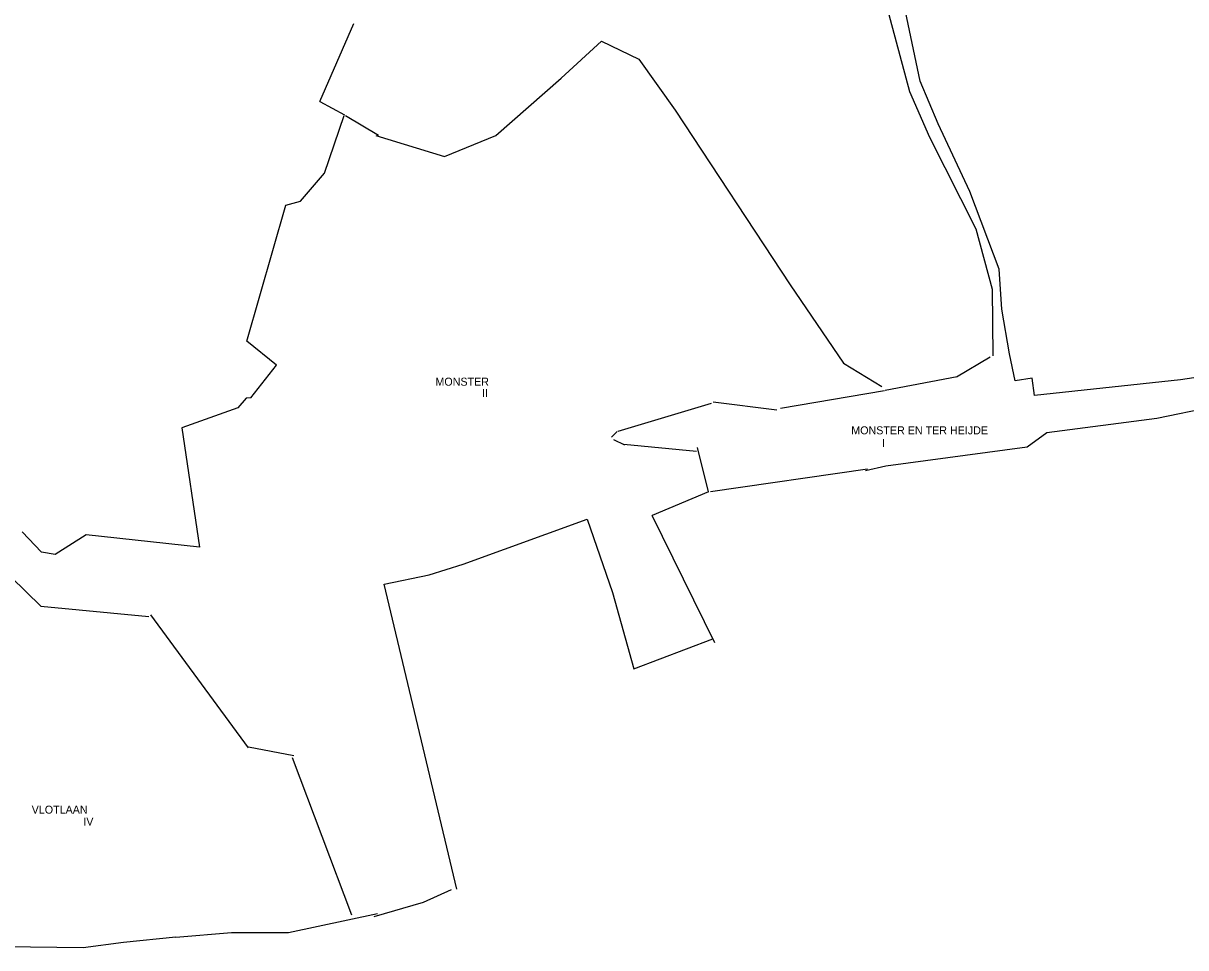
# Model space of a CAD drawing. Extents: x 69068 to 80855, y 440023 to 451362.
# Drawn here: x 71365 to 72673, y 448266 to 449305 of the extents above; entities that cross this region are included whole.
import ezdxf

# ---------------------------------------------------------------- set-up
doc = ezdxf.new("R2010")
doc.units = 0
for name, color, linetype in [('Bemalingsgebiedsgrens', 7, 'Continuous'), ('Bemalingsgebiedsnummer', 7, 'Continuous'), ('RIO_Leidingen', 7, 'Continuous')]:
    doc.layers.add(name, color=color, linetype=linetype)

msp = doc.modelspace()

# ---------------------------------------------------------------- linework, layer by layer
at = {"layer": 'Bemalingsgebiedsgrens'}
for p, q in [((72362.6, 449228.3), (72336.6, 449324.8)), ((72362.6, 449228.3), (72336.6, 449324.8)), ((72362.6, 449228.3), (72336.6, 449324.8)), ((72362.6, 449228.3), (72336.6, 449324.8)), ((71699, 449217.5), (71737.4, 449305)), ((71699, 449217.5), (71737.4, 449305)), ((71699, 449217.5), (71737.4, 449305)), ((71699, 449217.5), (71737.4, 449305)), ((71970.6, 449243.6), (72016, 449285.3)), ((71970.6, 449243.6), (72016, 449285.3)), ((71970.6, 449243.6), (72016, 449285.3)), ((71970.6, 449243.6), (72016, 449285.3)), ((72016, 449285.3), (72057.9, 449265)), ((72016, 449285.3), (72057.9, 449265)), ((72016, 449285.3), (72057.9, 449265)), ((72016, 449285.3), (72057.9, 449265)), ((72057.9, 449265), (72098.7, 449207.8)), ((72057.9, 449265), (72098.7, 449207.8)), ((72057.9, 449265), (72098.7, 449207.8)), ((72057.9, 449265), (72098.7, 449207.8)), ((71896.9, 449179.2), (71970.6, 449243.6)), ((71896.9, 449179.2), (71970.6, 449243.6)), ((71896.9, 449179.2), (71970.6, 449243.6)), ((71896.9, 449179.2), (71970.6, 449243.6)), ((72385.3, 449177), (72362.6, 449228.3)), ((72385.3, 449177), (72362.6, 449228.3)), ((72385.3, 449177), (72362.6, 449228.3)), ((72385.3, 449177), (72362.6, 449228.3)), ((71699, 449217.5), (71726.7, 449202.4)), ((71699, 449217.5), (71726.7, 449202.4)), ((71699, 449217.5), (71726.7, 449202.4)), ((71699, 449217.5), (71726.7, 449202.4)), ((71704.2, 449136.8), (71726.5, 449201.8)), ((71704.2, 449136.8), (71726.5, 449201.8)), ((71704.2, 449136.8), (71726.5, 449201.8)), ((71704.2, 449136.8), (71726.5, 449201.8)), ((71728, 449201.8), (71765, 449179.4)), ((71728, 449201.8), (71765, 449179.4)), ((71728, 449201.8), (71765, 449179.4)), ((71728, 449201.8), (71765, 449179.4)), ((72098.7, 449207.8), (72228, 449011.2)), ((72098.7, 449207.8), (72228, 449011.2)), ((72098.7, 449207.8), (72228, 449011.2)), ((72098.7, 449207.8), (72228, 449011.2)), ((71762, 449179.2), (71839.1, 449155.4)), ((71762, 449179.2), (71839.1, 449155.4)), ((71762, 449179.2), (71839.1, 449155.4)), ((71762, 449179.2), (71839.1, 449155.4)), ((71839.1, 449155.4), (71896.9, 449179.2)), ((71839.1, 449155.4), (71896.9, 449179.2)), ((71839.1, 449155.4), (71896.9, 449179.2)), ((71839.1, 449155.4), (71896.9, 449179.2)), ((72437.4, 449073.8), (72385.3, 449177)), ((72437.4, 449073.8), (72385.3, 449177)), ((72437.4, 449073.8), (72385.3, 449177)), ((72437.4, 449073.8), (72385.3, 449177)), ((71677.3, 449105.5), (71704.2, 449136.8)), ((71677.3, 449105.5), (71704.2, 449136.8)), ((71677.3, 449105.5), (71704.2, 449136.8)), ((71677.3, 449105.5), (71704.2, 449136.8)), ((71616.8, 448947.8), (71660.9, 449100.7)), ((71616.8, 448947.8), (71660.9, 449100.7)), ((71616.8, 448947.8), (71660.9, 449100.7)), ((71616.8, 448947.8), (71660.9, 449100.7)), ((71660.9, 449100.7), (71677.3, 449105.5)), ((71660.9, 449100.7), (71677.3, 449105.5)), ((71660.9, 449100.7), (71677.3, 449105.5)), ((71660.9, 449100.7), (71677.3, 449105.5)), ((72455.5, 449005.9), (72437.4, 449073.8)), ((72455.5, 449005.9), (72437.4, 449073.8)), ((72455.5, 449005.9), (72437.4, 449073.8)), ((72455.5, 449005.9), (72437.4, 449073.8)), ((72228, 449011.2), (72288.1, 448923)), ((72228, 449011.2), (72288.1, 448923)), ((72228, 449011.2), (72288.1, 448923)), ((72228, 449011.2), (72288.1, 448923)), ((72456.2, 448931.2), (72455.5, 449005.9)), ((72456.2, 448931.2), (72455.5, 449005.9)), ((72456.2, 448931.2), (72455.5, 449005.9)), ((72456.2, 448931.2), (72455.5, 449005.9)), ((71650.4, 448920.7), (71616.8, 448947.8)), ((71650.4, 448920.7), (71616.8, 448947.8)), ((71650.4, 448920.7), (71616.8, 448947.8)), ((71650.4, 448920.7), (71616.8, 448947.8)), ((72415, 448907.8), (72452.9, 448930.3)), ((72415, 448907.8), (72452.9, 448930.3)), ((72415, 448907.8), (72452.9, 448930.3)), ((72415, 448907.8), (72452.9, 448930.3)), ((71621.5, 448884), (71650.4, 448920.7)), ((71621.5, 448884), (71650.4, 448920.7)), ((71621.5, 448884), (71650.4, 448920.7)), ((71621.5, 448884), (71650.4, 448920.7)), ((72288.1, 448923), (72331.1, 448896.9)), ((72288.1, 448923), (72331.1, 448896.9)), ((72288.1, 448923), (72331.1, 448896.9)), ((72288.1, 448923), (72331.1, 448896.9)), ((72416, 448907.9), (72334.9, 448892.4)), ((72416, 448907.9), (72334.9, 448892.4)), ((72416, 448907.9), (72334.9, 448892.4)), ((72416, 448907.9), (72334.9, 448892.4)), ((72217.3, 448872.7), (72334, 448892.4)), ((72217.3, 448872.7), (72334, 448892.4)), ((72217.3, 448872.7), (72334, 448892.4)), ((72217.3, 448872.7), (72334, 448892.4)), ((71607, 448873), (71544, 448850.4)), ((71607, 448873), (71544, 448850.4)), ((71607, 448873), (71544, 448850.4)), ((71607, 448873), (71544, 448850.4)), ((71616.2, 448883.7), (71607, 448873)), ((71616.2, 448883.7), (71607, 448873)), ((71616.2, 448883.7), (71607, 448873)), ((71616.2, 448883.7), (71607, 448873)), ((71621.5, 448884), (71616.2, 448883.7)), ((71621.5, 448884), (71616.2, 448883.7)), ((71621.5, 448884), (71616.2, 448883.7)), ((71621.5, 448884), (71616.2, 448883.7)), ((72034.7, 448846.5), (72139.7, 448878.3)), ((72034.7, 448846.5), (72139.7, 448878.3)), ((72034.7, 448846.5), (72139.7, 448878.3)), ((72034.7, 448846.5), (72139.7, 448878.3)), ((72141.6, 448879.7), (72213.1, 448870.8)), ((72141.6, 448879.7), (72213.1, 448870.8)), ((72141.6, 448879.7), (72213.1, 448870.8)), ((72141.6, 448879.7), (72213.1, 448870.8)), ((71544, 448850.4), (71563.9, 448716.3)), ((71544, 448850.4), (71563.9, 448716.3)), ((71544, 448850.4), (71563.9, 448716.3)), ((71544, 448850.4), (71563.9, 448716.3)), ((72027, 448840), (72033.5, 448846.3)), ((72027, 448840), (72033.5, 448846.3)), ((72027, 448840), (72033.5, 448846.3)), ((72027, 448840), (72033.5, 448846.3)), ((72029.3, 448837.4), (72041.7, 448831.3)), ((72029.3, 448837.4), (72041.7, 448831.3)), ((72029.3, 448837.4), (72041.7, 448831.3)), ((72029.3, 448837.4), (72041.7, 448831.3)), ((72122.8, 448823.8), (72041, 448831.8)), ((72122.8, 448823.8), (72041, 448831.8)), ((72122.8, 448823.8), (72041, 448831.8)), ((72122.8, 448823.8), (72041, 448831.8)), ((72136.3, 448778.4), (72124, 448828.1)), ((72136.3, 448778.4), (72124, 448828.1)), ((72136.3, 448778.4), (72124, 448828.1)), ((72136.3, 448778.4), (72124, 448828.1)), ((72138.4, 448778.8), (72315, 448804.2)), ((72138.4, 448778.8), (72315, 448804.2)), ((72138.4, 448778.8), (72315, 448804.2)), ((72138.4, 448778.8), (72315, 448804.2)), ((72136.1, 448778.4), (72073, 448751.7)), ((72136.1, 448778.4), (72073, 448751.7)), ((72136.1, 448778.4), (72073, 448751.7)), ((72136.1, 448778.4), (72073, 448751.7)), ((72143.3, 448608.6), (72073, 448751.7)), ((72143.3, 448608.6), (72073, 448751.7)), ((72143.3, 448608.6), (72073, 448751.7)), ((72143.3, 448608.6), (72073, 448751.7)), ((71386.1, 448710.7), (71364.3, 448733.6)), ((71386.1, 448710.7), (71364.3, 448733.6)), ((71386.1, 448710.7), (71364.3, 448733.6)), ((71386.1, 448710.7), (71364.3, 448733.6)), ((71436.4, 448730.2), (71401.5, 448708.1)), ((71436.4, 448730.2), (71401.5, 448708.1)), ((71436.4, 448730.2), (71401.5, 448708.1)), ((71436.4, 448730.2), (71401.5, 448708.1)), ((71563.9, 448716.3), (71436.4, 448730.2)), ((71563.9, 448716.3), (71436.4, 448730.2)), ((71563.9, 448716.3), (71436.4, 448730.2)), ((71563.9, 448716.3), (71436.4, 448730.2)), ((71401.5, 448708.1), (71386.1, 448710.7)), ((71401.5, 448708.1), (71386.1, 448710.7)), ((71401.5, 448708.1), (71386.1, 448710.7)), ((71401.5, 448708.1), (71386.1, 448710.7)), ((71508.6, 448640.1), (71618.4, 448490.5)), ((71508.6, 448640.1), (71618.4, 448490.5)), ((71508.6, 448640.1), (71618.4, 448490.5)), ((71508.6, 448640.1), (71618.4, 448490.5)), ((71618.9, 448491.5), (71669.8, 448481.8)), ((71618.9, 448491.5), (71669.8, 448481.8)), ((71618.9, 448491.5), (71669.8, 448481.8)), ((71618.9, 448491.5), (71669.8, 448481.8)), ((71815.5, 448317.1), (71847.2, 448331.3)), ((71815.5, 448317.1), (71847.2, 448331.3)), ((71815.5, 448317.1), (71847.2, 448331.3)), ((71815.5, 448317.1), (71847.2, 448331.3)), ((71760.3, 448300.7), (71815.5, 448317.1)), ((71760.3, 448300.7), (71815.5, 448317.1)), ((71760.3, 448300.7), (71815.5, 448317.1)), ((71760.3, 448300.7), (71815.5, 448317.1)), ((71663.7, 448282.9), (71763.8, 448304.1)), ((71663.7, 448282.9), (71763.8, 448304.1)), ((71663.7, 448282.9), (71763.8, 448304.1)), ((71663.7, 448282.9), (71763.8, 448304.1)), ((71537.1, 448277.5), (71599.6, 448282.9)), ((71537.1, 448277.5), (71599.6, 448282.9)), ((71537.1, 448277.5), (71599.6, 448282.9)), ((71537.1, 448277.5), (71599.6, 448282.9)), ((71599.6, 448282.9), (71663.7, 448282.9)), ((71599.6, 448282.9), (71663.7, 448282.9)), ((71599.6, 448282.9), (71663.7, 448282.9)), ((71599.6, 448282.9), (71663.7, 448282.9))]:
    msp.add_line(p, q, dxfattribs=at)
for points in [[(73113.5, 448972.1), (72993.5, 448964.8), (72895.4, 448937.3), (72837.5, 448929.9), (72667.2, 448904.2), (72502.7, 448886.9), (72500.3, 448906.4), (72481.2, 448903.2), (72474.7, 448933.7), (72466, 448983.7), (72463.3, 449028.9), (72430.3, 449116.2), (72394.4, 449192.2), (72374.1, 449240.4), (72357.7, 449318.6)], [(73113.5, 448972.1), (72993.5, 448964.8), (72895.4, 448937.3), (72837.5, 448929.9), (72667.2, 448904.2), (72502.7, 448886.9), (72500.3, 448906.4), (72481.2, 448903.2), (72474.7, 448933.7), (72466, 448983.7), (72463.3, 449028.9), (72430.3, 449116.2), (72394.4, 449192.2), (72374.1, 449240.4), (72357.7, 449318.6)], [(73113.5, 448972.1), (72993.5, 448964.8), (72895.4, 448937.3), (72837.5, 448929.9), (72667.2, 448904.2), (72502.7, 448886.9), (72500.3, 448906.4), (72481.2, 448903.2), (72474.7, 448933.7), (72466, 448983.7), (72463.3, 449028.9), (72430.3, 449116.2), (72394.4, 449192.2), (72374.1, 449240.4), (72357.7, 449318.6)], [(73113.5, 448972.1), (72993.5, 448964.8), (72895.4, 448937.3), (72837.5, 448929.9), (72667.2, 448904.2), (72502.7, 448886.9), (72500.3, 448906.4), (72481.2, 448903.2), (72474.7, 448933.7), (72466, 448983.7), (72463.3, 449028.9), (72430.3, 449116.2), (72394.4, 449192.2), (72374.1, 449240.4), (72357.7, 449318.6)], [(72335.6, 448807.6), (72494.8, 448829), (72516.7, 448845.2), (72640.5, 448861.4), (73011.7, 448937.9), (73195.3, 448943.3), (73322.3, 448970.6), (73309.6, 449010.8)], [(72312.7, 448802.5), (72335.6, 448807.6)], [(72312.7, 448802.5), (72335.6, 448807.6)], [(72312.7, 448802.5), (72335.6, 448807.6)], [(72312.7, 448802.5), (72335.6, 448807.6)], [(71853.1, 448331.6), (71771.3, 448674.4), (71822.1, 448685.1), (71860.1, 448697.1), (71999.9, 448747.8)], [(71853.1, 448331.6), (71771.3, 448674.4), (71822.1, 448685.1), (71860.1, 448697.1), (71999.9, 448747.8)], [(71853.1, 448331.6), (71771.3, 448674.4), (71822.1, 448685.1), (71860.1, 448697.1), (71999.9, 448747.8)], [(71853.1, 448331.6), (71771.3, 448674.4), (71822.1, 448685.1), (71860.1, 448697.1), (71999.9, 448747.8)], [(71999.9, 448747.8), (72028.1, 448665.2), (72052.4, 448579.4), (72141.1, 448613.2)], [(71999.9, 448747.8), (72028.1, 448665.2), (72052.4, 448579.4), (72141.1, 448613.2)], [(71999.9, 448747.8), (72028.1, 448665.2), (72052.4, 448579.4), (72141.1, 448613.2)], [(71999.9, 448747.8), (72028.1, 448665.2), (72052.4, 448579.4), (72141.1, 448613.2)], [(71319.2, 448665.5), (71342.7, 448684.3), (71351.8, 448682.6), (71385.1, 448649.9), (71506.8, 448638.3)], [(71319.2, 448665.5), (71342.7, 448684.3), (71351.8, 448682.6), (71385.1, 448649.9), (71506.8, 448638.3)], [(71319.2, 448665.5), (71342.7, 448684.3), (71351.8, 448682.6), (71385.1, 448649.9), (71506.8, 448638.3)], [(71319.2, 448665.5), (71342.7, 448684.3), (71351.8, 448682.6), (71385.1, 448649.9), (71506.8, 448638.3)], [(71537.1, 448277.5), (71478.2, 448271.7), (71432.9, 448265.7), (71373.6, 448266.4), (71323.6, 448267), (71280.9, 448270.4), (71245.6, 448277.7), (71220.2, 448286.2), (71205.5, 448287), (71137.4, 448315), (71104.9, 448332.3), (71071.7, 448351.7), (71018.8, 448387.5), (70978, 448424.9), (70915.3, 448471.7), (70856.5, 448503.9), (70777, 448514.7), (70731.5, 448543.4), (70728.9, 448547.5)], [(71537.1, 448277.5), (71478.2, 448271.7), (71432.9, 448265.7), (71373.6, 448266.4), (71323.6, 448267), (71280.9, 448270.4), (71245.6, 448277.7), (71220.2, 448286.2), (71205.5, 448287), (71137.4, 448315), (71104.9, 448332.3), (71071.7, 448351.7), (71018.8, 448387.5), (70978, 448424.9), (70915.3, 448471.7), (70856.5, 448503.9), (70777, 448514.7), (70731.5, 448543.4), (70728.9, 448547.5)], [(71537.1, 448277.5), (71478.2, 448271.7), (71432.9, 448265.7), (71373.6, 448266.4), (71323.6, 448267), (71280.9, 448270.4), (71245.6, 448277.7), (71220.2, 448286.2), (71205.5, 448287), (71137.4, 448315), (71104.9, 448332.3), (71071.7, 448351.7), (71018.8, 448387.5), (70978, 448424.9), (70915.3, 448471.7), (70856.5, 448503.9), (70777, 448514.7), (70731.5, 448543.4), (70728.9, 448547.5)], [(71537.1, 448277.5), (71478.2, 448271.7), (71432.9, 448265.7), (71373.6, 448266.4), (71323.6, 448267), (71280.9, 448270.4), (71245.6, 448277.7), (71220.2, 448286.2), (71205.5, 448287), (71137.4, 448315), (71104.9, 448332.3), (71071.7, 448351.7), (71018.8, 448387.5), (70978, 448424.9), (70915.3, 448471.7), (70856.5, 448503.9), (70777, 448514.7), (70731.5, 448543.4), (70728.9, 448547.5)], [(71735.1, 448302.3), (71668.3, 448479.2)], [(71735.1, 448302.3), (71668.3, 448479.2)], [(71735.1, 448302.3), (71668.3, 448479.2)], [(71735.1, 448302.3), (71668.3, 448479.2)]]:
    msp.add_lwpolyline(points, dxfattribs=at)

# ---------------------------------------------------------------- texts
at = {"layer": 'Bemalingsgebiedsnummer'}
for s, p in [(' II', (71878.1, 448884.9)), (' II', (71878.1, 448884.9)), (' II', (71878.1, 448884.9)), (' II', (71878.1, 448884.9)), (' I', (72328.2, 448828.7)), (' I', (72328.2, 448828.7)), (' I', (72328.2, 448828.7)), (' I', (72328.2, 448828.7)), ('IV ', (71433.1, 448403.1)), ('IV ', (71433.1, 448403.1)), ('IV ', (71433.1, 448403.1)), ('IV ', (71433.1, 448403.1))]:
    msp.add_text(s, height=9, dxfattribs=at).set_placement(p)
at = {"layer": 'RIO_Leidingen'}
for s, p in [('MONSTER', (71829.1, 448897.8)), ('MONSTER', (71829.1, 448897.8)), ('MONSTER', (71829.1, 448897.8)), ('MONSTER', (71829.1, 448897.8)), ('MONSTER EN TER HEIJDE', (72296.8, 448843.1)), ('MONSTER EN TER HEIJDE', (72296.8, 448843.1)), ('MONSTER EN TER HEIJDE', (72296.8, 448843.1)), ('MONSTER EN TER HEIJDE', (72296.8, 448843.1)), ('VLOTLAAN', (71375, 448416.5)), ('VLOTLAAN', (71375, 448416.5)), ('VLOTLAAN', (71375, 448416.5)), ('VLOTLAAN', (71375, 448416.5))]:
    msp.add_text(s, height=9, dxfattribs=at).set_placement(p)

doc.saveas('drawing.dxf')
